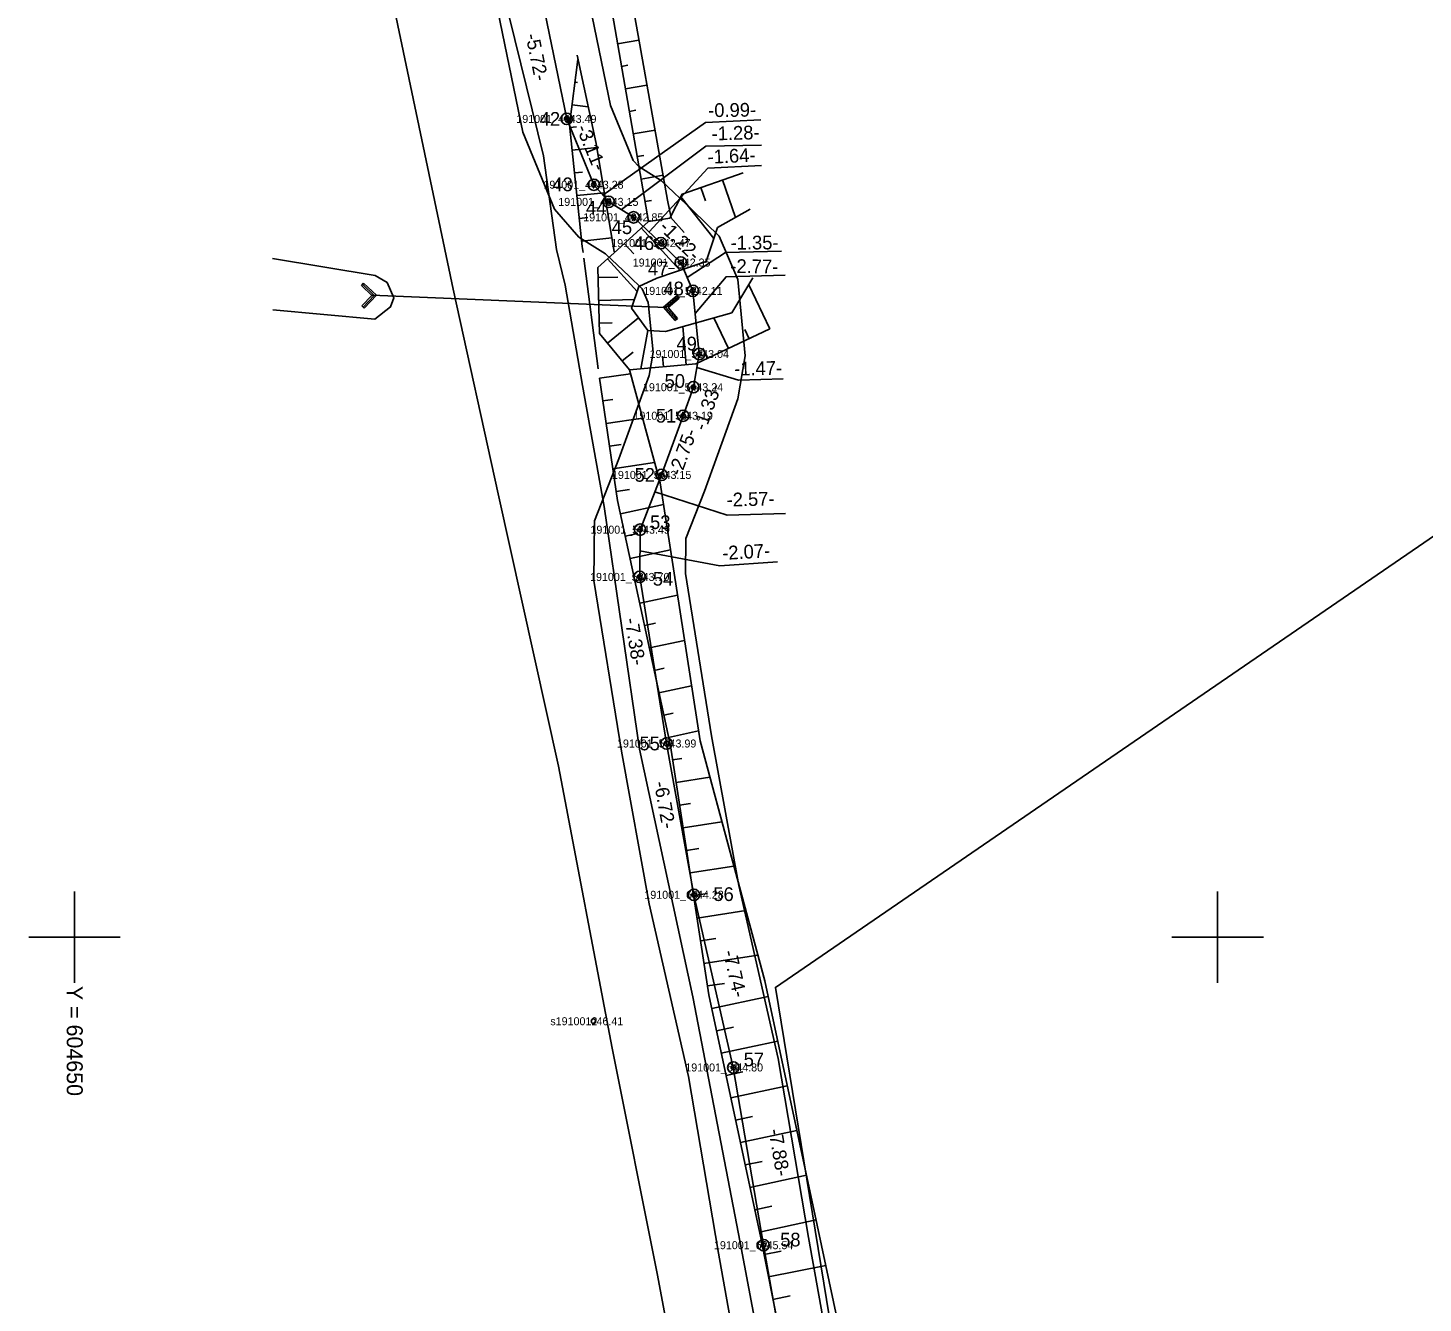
# Model space of a CAD drawing. Extents: x 604066 to 604956, y 6473634 to 6474346.
# Drawn here: x 604648 to 604709, y 6473734 to 6473789.8 of the extents above; entities that cross this region are included whole.
import ezdxf

# ---------------------------------------------------------------- set-up
doc = ezdxf.new("R2010")
doc.units = 0
for name, color, linetype in [('HALJASTUS', 7, 'Continuous'), ('JOONSIDE', 7, 'Continuous'), ('KOORDPUNKT', 7, 'Continuous'), ('MOOTKORG', 7, 'Continuous'), ('MOOTMPUNKT', 7, 'Continuous'), ('MOOTNR', 7, 'Continuous'), ('MOOTPIIR', 7, 'Continuous'), ('PIIR', 7, 'Continuous'), ('RELJEEF', 7, 'Continuous'), ('SITRASS', 7, 'Continuous'), ('TEE', 7, 'Continuous'), ('TRUUP', 7, 'Continuous'), ('VEEKOGU', 7, 'Continuous'), ('VORK', 7, 'Continuous')]:
    doc.layers.add(name, color=color, linetype=linetype)

msp = doc.modelspace()

# ---------------------------------------------------------------- linework, layer by layer
at = {"layer": 'HALJASTUS'}
msp.add_lwpolyline([(604673.598, 6473779.97), (604672.824, 6473784.706), (604671.983, 6473788.559)], dxfattribs=at)
at = {"layer": 'JOONSIDE'}
for points in [[(604673.105, 6473782.446), (604677.594, 6473785.615), (604680.025, 6473785.739)], [(604673.921, 6473781.809), (604677.611, 6473784.586), (604680.053, 6473784.632)], [(604675.133, 6473780.834), (604677.709, 6473783.622), (604680.053, 6473783.733)], [(604676.796, 6473778.845), (604678.469, 6473779.934), (604680.917, 6473779.999)], [(604677.146, 6473777.274), (604678.501, 6473778.872), (604681.081, 6473778.937)], [(604677.22, 6473774.9), (604679.04, 6473774.347), (604680.998, 6473774.409)], [(604675.391, 6473769.475), (604678.542, 6473768.445), (604681.105, 6473768.527)], [(604674.73, 6473766.892), (604678.232, 6473766.24), (604680.746, 6473766.403)]]:
    msp.add_lwpolyline(points, dxfattribs=at)
at = {"layer": 'KOORDPUNKT'}
for centre, radius in [((604671.53, 6473785.776), 0.25), ((604671.53, 6473785.776), 0.025), ((604671.53, 6473785.776), 0.0221), ((604671.53, 6473785.776), 0.0191), ((604671.53, 6473785.776), 0.0161), ((604671.53, 6473785.776), 0.0132), ((604671.53, 6473785.776), 0.0102), ((604671.53, 6473785.776), 0.00726), ((604671.53, 6473785.776), 0.0043), ((604672.715, 6473782.898), 0.25), ((604672.715, 6473782.898), 0.025), ((604672.715, 6473782.898), 0.0221), ((604672.715, 6473782.898), 0.0191), ((604672.715, 6473782.898), 0.0161), ((604672.715, 6473782.898), 0.0132), ((604672.715, 6473782.898), 0.0102), ((604672.715, 6473782.898), 0.00726), ((604672.715, 6473782.898), 0.0043), ((604673.365, 6473782.149), 0.25), ((604673.365, 6473782.149), 0.025), ((604673.365, 6473782.149), 0.0221), ((604673.365, 6473782.149), 0.0191), ((604673.365, 6473782.149), 0.0161), ((604673.365, 6473782.149), 0.0132), ((604673.365, 6473782.149), 0.0102), ((604673.365, 6473782.149), 0.00726), ((604673.365, 6473782.149), 0.0043), ((604674.456, 6473781.473), 0.25), ((604674.456, 6473781.473), 0.025), ((604674.456, 6473781.473), 0.0221), ((604674.456, 6473781.473), 0.0191), ((604674.456, 6473781.473), 0.0161), ((604674.456, 6473781.473), 0.0132), ((604674.456, 6473781.473), 0.0102), ((604674.456, 6473781.473), 0.00726), ((604674.456, 6473781.473), 0.0043), ((604675.648, 6473780.347), 0.25), ((604675.648, 6473780.347), 0.025), ((604675.648, 6473780.347), 0.0221), ((604675.648, 6473780.347), 0.0191), ((604675.648, 6473780.347), 0.0161), ((604675.648, 6473780.347), 0.0132), ((604675.648, 6473780.347), 0.0102), ((604675.648, 6473780.347), 0.00726), ((604675.648, 6473780.347), 0.0043), ((604676.518, 6473779.496), 0.25), ((604676.518, 6473779.496), 0.025), ((604676.518, 6473779.496), 0.0221), ((604676.518, 6473779.496), 0.0191), ((604676.518, 6473779.496), 0.0161), ((604676.518, 6473779.496), 0.0132), ((604676.518, 6473779.496), 0.0102), ((604676.518, 6473779.496), 0.00726), ((604676.518, 6473779.496), 0.0043), ((604677.048, 6473778.257), 0.25), ((604677.048, 6473778.257), 0.025), ((604677.048, 6473778.257), 0.0221), ((604677.048, 6473778.257), 0.0191), ((604677.048, 6473778.257), 0.0161), ((604677.048, 6473778.257), 0.0132), ((604677.048, 6473778.257), 0.0102), ((604677.048, 6473778.257), 0.00726), ((604677.048, 6473778.257), 0.0043), ((604677.324, 6473775.497), 0.25), ((604677.324, 6473775.497), 0.025), ((604677.324, 6473775.497), 0.0221), ((604677.324, 6473775.497), 0.0191), ((604677.324, 6473775.497), 0.0161), ((604677.324, 6473775.497), 0.0132), ((604677.324, 6473775.497), 0.0102), ((604677.324, 6473775.497), 0.00726), ((604677.324, 6473775.497), 0.0043), ((604677.07, 6473774.045), 0.25), ((604677.07, 6473774.045), 0.025), ((604677.07, 6473774.045), 0.0221), ((604677.07, 6473774.045), 0.0191), ((604677.07, 6473774.045), 0.0161), ((604677.07, 6473774.045), 0.0132), ((604677.07, 6473774.045), 0.0102), ((604677.07, 6473774.045), 0.00726), ((604677.07, 6473774.045), 0.0043), ((604676.621, 6473772.798), 0.25), ((604676.621, 6473772.798), 0.025), ((604676.621, 6473772.798), 0.0221), ((604676.621, 6473772.798), 0.0191), ((604676.621, 6473772.798), 0.0161), ((604676.621, 6473772.798), 0.0132), ((604676.621, 6473772.798), 0.0102), ((604676.621, 6473772.798), 0.00726), ((604676.621, 6473772.798), 0.0043), ((604675.68, 6473770.211), 0.25), ((604675.68, 6473770.211), 0.025), ((604675.68, 6473770.211), 0.0221), ((604675.68, 6473770.211), 0.0191), ((604675.68, 6473770.211), 0.0161), ((604675.68, 6473770.211), 0.0132), ((604675.68, 6473770.211), 0.0102), ((604675.68, 6473770.211), 0.00726), ((604675.68, 6473770.211), 0.0043), ((604674.738, 6473767.815), 0.25), ((604674.738, 6473767.815), 0.025), ((604674.738, 6473767.815), 0.0221), ((604674.738, 6473767.815), 0.0191), ((604674.738, 6473767.815), 0.0161), ((604674.738, 6473767.815), 0.0132), ((604674.738, 6473767.815), 0.0102), ((604674.738, 6473767.815), 0.00726), ((604674.738, 6473767.815), 0.0043), ((604674.721, 6473765.75), 0.25), ((604674.721, 6473765.75), 0.025), ((604674.721, 6473765.75), 0.0221), ((604674.721, 6473765.75), 0.0191), ((604674.721, 6473765.75), 0.0161), ((604674.721, 6473765.75), 0.0132), ((604674.721, 6473765.75), 0.0102), ((604674.721, 6473765.75), 0.00726), ((604674.721, 6473765.75), 0.0043), ((604675.898, 6473758.467), 0.25), ((604675.898, 6473758.467), 0.025), ((604675.898, 6473758.467), 0.0221), ((604675.898, 6473758.467), 0.0191), ((604675.898, 6473758.467), 0.0161), ((604675.898, 6473758.467), 0.0132), ((604675.898, 6473758.467), 0.0102), ((604675.898, 6473758.467), 0.00726), ((604675.898, 6473758.467), 0.0043), ((604677.095, 6473751.852), 0.25), ((604677.095, 6473751.852), 0.025), ((604677.095, 6473751.852), 0.0221), ((604677.095, 6473751.852), 0.0191), ((604677.095, 6473751.852), 0.0161), ((604677.095, 6473751.852), 0.0132), ((604677.095, 6473751.852), 0.0102), ((604677.095, 6473751.852), 0.00726), ((604677.095, 6473751.852), 0.0043), ((604678.816, 6473744.303), 0.25), ((604678.816, 6473744.303), 0.025), ((604678.816, 6473744.303), 0.0221), ((604678.816, 6473744.303), 0.0191), ((604678.816, 6473744.303), 0.0161), ((604678.816, 6473744.303), 0.0132), ((604678.816, 6473744.303), 0.0102), ((604678.816, 6473744.303), 0.00726), ((604678.816, 6473744.303), 0.0043), ((604680.141, 6473736.532), 0.25), ((604680.141, 6473736.532), 0.025), ((604680.141, 6473736.532), 0.0221), ((604680.141, 6473736.532), 0.0191), ((604680.141, 6473736.532), 0.0161), ((604680.141, 6473736.532), 0.0132), ((604680.141, 6473736.532), 0.0102), ((604680.141, 6473736.532), 0.00726), ((604680.141, 6473736.532), 0.0043)]:
    msp.add_circle(centre, radius, dxfattribs=at)
at = {"layer": 'MOOTMPUNKT'}
for centre in [(604671.53, 6473785.776), (604672.715, 6473782.898), (604673.365, 6473782.149), (604674.456, 6473781.473), (604675.648, 6473780.347), (604676.518, 6473779.496), (604677.048, 6473778.257), (604677.324, 6473775.497), (604677.07, 6473774.045), (604676.621, 6473772.798), (604675.68, 6473770.211), (604674.738, 6473767.815), (604674.721, 6473765.75), (604675.898, 6473758.467), (604677.095, 6473751.852), (604672.703, 6473746.324), (604678.816, 6473744.303), (604680.141, 6473736.532)]:
    msp.add_circle(centre, 0.1, dxfattribs=at)
at = {"layer": 'MOOTPIIR'}
for points in [[(604683.46, 6473729.306), (604682.111, 6473736.875), (604680.778, 6473744.694), (604679.055, 6473752.253), (604677.869, 6473758.805), (604676.722, 6473765.902), (604676.735, 6473767.428), (604677.551, 6473769.503), (604678.502, 6473772.117), (604679.01, 6473773.53), (604679.341, 6473775.423), (604679.008, 6473778.761), (604678.201, 6473780.648), (604677.034, 6473781.789), (604675.682, 6473783.066), (604674.677, 6473783.689), (604674.44, 6473783.962), (604673.451, 6473786.363), (604672.342, 6473791.755)], [(604668.412, 6473791.009), (604669.609, 6473785.189), (604670.99, 6473781.834), (604672.053, 6473780.609), (604673.23, 6473779.88), (604674.262, 6473778.905), (604674.835, 6473778.344), (604675.088, 6473777.753), (604675.307, 6473775.571), (604675.13, 6473774.56), (604674.74, 6473773.479), (604673.809, 6473770.919), (604672.741, 6473768.202), (604672.72, 6473765.598), (604673.927, 6473758.129), (604675.135, 6473751.451), (604676.854, 6473743.912), (604678.171, 6473736.189), (604679.54, 6473728.5)]]:
    msp.add_lwpolyline(points, dxfattribs=at)
at = {"layer": 'PIIR'}
msp.add_lwpolyline([(604833.54, 6473909.5), (604897.39, 6473936.49), (604953.49, 6473960.24), (604956.07, 6473961.29), (604940.8, 6473724.06), (604687.73, 6473704.56), (604680.66, 6473747.8), (604821.94, 6473844.68)], close=True, dxfattribs=at)
msp.add_lwpolyline([(604392.23, 6473874.61), (604414.7, 6473872.41), (604426.55, 6473871.03), (604444.65, 6473869.66), (604482.63, 6473866.81), (604486.98, 6473866.41), (604549.55, 6473854.82), (604575.16, 6473852.02), (604645.55, 6473867.92), (604659, 6473875.69), (604714.62, 6473889.17), (604776, 6473903.81), (604824.84, 6473905.94), (604833.54, 6473909.5), (604821.94, 6473844.68), (604680.66, 6473747.8), (604687.73, 6473704.56), (604422.99, 6473691.29), (604421.99, 6473694.09), (604395.15, 6473723.9)], dxfattribs=at)
at = {"layer": 'RELJEEF'}
for p, q in [((604673.757, 6473789.058), (604674.688, 6473789.219)), ((604673.927, 6473788.072), (604674.208, 6473788.121)), ((604671.894, 6473787.388), (604672, 6473787.374)), ((604674.098, 6473787.087), (604675.04, 6473787.25)), ((604671.765, 6473786.396), (604672.475, 6473786.304)), ((604674.269, 6473786.102), (604674.553, 6473786.151)), ((604671.662, 6473785.404), (604671.958, 6473785.435)), ((604674.44, 6473785.116), (604675.392, 6473785.282)), ((604671.767, 6473784.41), (604672.854, 6473784.524)), ((604674.611, 6473784.131), (604674.898, 6473784.181)), ((604671.872, 6473783.415), (604672.215, 6473783.451)), ((604674.781, 6473783.146), (604675.744, 6473783.313)), ((604678.342, 6473783.106), (604678.913, 6473781.471)), ((604671.977, 6473782.421), (604673.177, 6473782.547)), ((604674.952, 6473782.161), (604675.243, 6473782.211)), ((604676.521, 6473782.37), (604677.966, 6473780.549)), ((604677.398, 6473782.776), (604677.599, 6473782.201)), ((604672.082, 6473781.426), (604672.459, 6473781.466)), ((604674.785, 6473781.006), (604676.483, 6473779.156)), ((604676.065, 6473781.48), (604676.661, 6473780.813)), ((604672.186, 6473780.432), (604673.5, 6473780.57)), ((604674.048, 6473780.33), (604674.469, 6473779.871)), ((604673.308, 6473779.657), (604674.604, 6473778.223)), ((604672.908, 6473778.839), (604673.763, 6473778.86)), ((604680.412, 6473776.595), (604679.494, 6473778.527)), ((604672.932, 6473777.84), (604674.489, 6473777.877)), ((604672.956, 6473776.84), (604673.513, 6473776.853)), ((604673.32, 6473775.966), (604674.675, 6473777.075)), ((604676.76, 6473775.023), (604676.613, 6473776.696)), ((604678.606, 6473775.737), (604677.967, 6473777.08)), ((604674.768, 6473774.848), (604675.072, 6473776.521)), ((604679.509, 6473776.166), (604679.318, 6473776.568)), ((604673.953, 6473775.192), (604674.432, 6473775.584)), ((604677.702, 6473775.307), (604677.489, 6473775.756)), ((604675.764, 6473774.935), (604675.723, 6473775.403)), ((604672.964, 6473774.437), (604674.316, 6473774.637)), ((604673.11, 6473773.448), (604673.551, 6473773.513)), ((604673.256, 6473772.458), (604674.843, 6473772.693)), ((604673.403, 6473771.469), (604673.914, 6473771.545)), ((604673.549, 6473770.48), (604675.37, 6473770.749)), ((604673.695, 6473769.491), (604674.274, 6473769.576)), ((604673.879, 6473768.508), (604675.758, 6473768.913)), ((604674.09, 6473767.531), (604674.637, 6473767.649)), ((604674.301, 6473766.553), (604676.065, 6473766.934)), ((604674.512, 6473765.576), (604675.024, 6473765.686)), ((604674.722, 6473764.598), (604676.373, 6473764.954)), ((604674.933, 6473763.621), (604675.411, 6473763.724)), ((604675.144, 6473762.643), (604676.681, 6473762.974)), ((604675.355, 6473761.666), (604675.799, 6473761.761)), ((604675.565, 6473760.688), (604676.988, 6473760.995)), ((604675.776, 6473759.711), (604676.186, 6473759.799)), ((604675.987, 6473758.733), (604677.296, 6473759.015)), ((604676.161, 6473757.749), (604676.572, 6473757.812)), ((604676.314, 6473756.76), (604677.793, 6473756.989)), ((604676.466, 6473755.772), (604676.943, 6473755.846)), ((604676.619, 6473754.784), (604678.317, 6473755.046)), ((604676.771, 6473753.795), (604677.313, 6473753.879)), ((604676.924, 6473752.807), (604678.84, 6473753.103)), ((604677.076, 6473751.819), (604677.684, 6473751.913)), ((604677.229, 6473750.831), (604679.363, 6473751.16)), ((604677.381, 6473749.842), (604678.054, 6473749.946)), ((604677.534, 6473748.854), (604679.887, 6473749.217)), ((604677.686, 6473747.866), (604678.425, 6473747.98)), ((604677.873, 6473746.884), (604680.337, 6473747.41)), ((604678.082, 6473745.906), (604678.822, 6473746.064)), ((604678.291, 6473744.928), (604680.758, 6473745.454)), ((604678.5, 6473743.95), (604679.24, 6473744.108)), ((604678.708, 6473742.972), (604681.179, 6473743.499)), ((604678.917, 6473741.994), (604679.659, 6473742.152)), ((604679.126, 6473741.016), (604681.6, 6473741.544)), ((604679.335, 6473740.038), (604680.077, 6473740.197)), ((604679.544, 6473739.06), (604682.021, 6473739.589)), ((604679.752, 6473738.082), (604680.496, 6473738.241)), ((604679.961, 6473737.104), (604682.442, 6473737.634)), ((604680.16, 6473736.124), (604680.909, 6473736.273)), ((604680.355, 6473735.143), (604682.865, 6473735.643)), ((604680.551, 6473734.163), (604681.307, 6473734.313))]:
    msp.add_line(p, q, dxfattribs=at)
for points in [[(604653.295, 6473883.776), (604652.349, 6473882.704), (604651.554, 6473874.934), (604652.409, 6473867.668), (604653.905, 6473857.515), (604657.906, 6473844.822), (604660.747, 6473842.118), (604667.575, 6473831.749), (604666.639, 6473827.232), (604667.872, 6473819.034), (604671.628, 6473805.551), (604673.035, 6473793.22), (604675.102, 6473781.297)], [(604668.878, 6473831.498), (604668.326, 6473826.862), (604669.23, 6473819.524), (604672.734, 6473805.555), (604674.05, 6473792.791), (604675.939, 6473782.22), (604676.105, 6473781.446)], [(604672.022, 6473788.38), (604671.651, 6473785.513), (604672.211, 6473780.197), (604672.245, 6473779.94)], [(604675.102, 6473781.297), (604676.043, 6473781.437), (604676.583, 6473782.492), (604679.244, 6473783.42)], [(604680.412, 6473776.595), (604677.182, 6473775.06), (604674.271, 6473774.804), (604672.967, 6473776.398), (604672.897, 6473779.286), (604673.752, 6473780.058), (604675.102, 6473781.297)], [(604672.278, 6473779.683), (604672.91, 6473774.853)], [(604672.964, 6473774.437), (604673.755, 6473769.085), (604676.065, 6473758.371), (604677.745, 6473747.484), (604680.015, 6473736.852), (604681.936, 6473727.206), (604682.488, 6473725.191), (604683.769, 6473718.464), (604685.268, 6473712.216), (604687.251, 6473697.629), (604689.629, 6473693.548), (604694.355, 6473690.407), (604698.464, 6473689.524)], [(604674.271, 6473774.804), (604675.61, 6473769.864), (604677.362, 6473758.59), (604680.189, 6473748.095), (604682.491, 6473737.405), (604685.004, 6473725.567), (604685.959, 6473718.549), (604686.885, 6473712.629), (604687.127, 6473704.438), (604689.157, 6473697.674), (604693.127, 6473694.128), (604698.019, 6473692.845)]]:
    msp.add_lwpolyline(points, dxfattribs=at)
at = {"layer": 'SITRASS'}
msp.add_lwpolyline([(604670.377, 6473791.382), (604671.53, 6473785.776), (604672.715, 6473782.898), (604673.365, 6473782.149), (604674.456, 6473781.473), (604675.648, 6473780.347), (604676.518, 6473779.496), (604677.048, 6473778.257), (604677.324, 6473775.497), (604677.07, 6473774.045), (604676.621, 6473772.798), (604675.68, 6473770.211), (604674.738, 6473767.815), (604674.721, 6473765.75), (604675.898, 6473758.467), (604677.095, 6473751.852), (604678.816, 6473744.303), (604680.141, 6473736.532), (604681.5, 6473728.903)], dxfattribs=at)
at = {"layer": 'TEE'}
for points in [[(604658.81, 6473832.593), (604663.41, 6473815.739), (604666.276, 6473803.944), (604668.262, 6473793.278), (604670.517, 6473784.167), (604671.08, 6473780.073), (604671.455, 6473778.507), (604672.217, 6473774.119), (604673.164, 6473768.835), (604674.714, 6473758.225), (604677.044, 6473747.391), (604679.117, 6473736.654), (604680.917, 6473727.059), (604681.455, 6473724.996), (604682.501, 6473718.343), (604684.444, 6473711.751), (604685.117, 6473704.62), (604685.813, 6473699.835), (604686.179, 6473697.568), (604688.712, 6473692.868), (604693.859, 6473689.574), (604697.868, 6473688.858)], [(604654.602, 6473831.658), (604658.704, 6473815.393), (604661.338, 6473804.068), (604663.574, 6473792.578), (604666.567, 6473778.333), (604668.535, 6473769.378), (604671.171, 6473757.479), (604673.518, 6473745.143), (604675.484, 6473735.292), (604677.447, 6473724.836), (604678.32, 6473717.488), (604681.05, 6473699.828), (604680.918, 6473696.769), (604679.22, 6473692.841), (604676.23, 6473689.347), (604671.943, 6473687.313)]]:
    msp.add_lwpolyline(points, dxfattribs=at)
at = {"layer": 'TRUUP'}
for p, q in [((604662.55, 6473778.497), (604662.648, 6473778.6)), ((604663.112, 6473778.062), (604662.599, 6473778.549)), ((604663.213, 6473778.065), (604662.648, 6473778.6)), ((604663.011, 6473778.059), (604662.55, 6473778.497)), ((604662.574, 6473777.598), (604663.011, 6473778.059)), ((604662.625, 6473777.549), (604663.112, 6473778.062)), ((604662.677, 6473777.5), (604663.213, 6473778.065)), ((604663.011, 6473778.067), (604675.866, 6473777.537)), ((604676.355, 6473778.052), (604675.766, 6473777.544)), ((604676.402, 6473777.998), (604675.866, 6473777.537)), ((604676.448, 6473777.945), (604675.966, 6473777.53)), ((604676.448, 6473777.945), (604676.355, 6473778.052)), ((604662.574, 6473777.598), (604662.677, 6473777.5)), ((604675.766, 6473777.544), (604676.274, 6473776.955)), ((604675.866, 6473777.537), (604676.327, 6473777.001)), ((604675.966, 6473777.53), (604676.381, 6473777.048)), ((604676.381, 6473777.048), (604676.274, 6473776.955))]:
    msp.add_line(p, q, dxfattribs=at)
at = {"layer": 'VEEKOGU'}
for points in [[(604679.548, 6473781.829), (604678.124, 6473781.026), (604677.627, 6473779.547), (604676.374, 6473779.119)], [(604658.662, 6473779.671), (604663.149, 6473778.929), (604663.679, 6473778.616), (604663.966, 6473777.959), (604663.815, 6473777.559), (604663.134, 6473777.019), (604658.678, 6473777.434)], [(604676.374, 6473779.119), (604676.248, 6473779.076), (604675.467, 6473778.809), (604674.68, 6473778.454), (604674.366, 6473777.505), (604675.072, 6473776.521), (604675.857, 6473776.481), (604678.745, 6473777.301), (604679.674, 6473778.821)]]:
    msp.add_lwpolyline(points, dxfattribs=at)
at = {"layer": 'VORK'}
for p, q in [((604650, 6473752), (604650, 6473748)), ((604700, 6473752), (604700, 6473748)), ((604648, 6473750), (604652, 6473750)), ((604698, 6473750), (604702, 6473750))]:
    msp.add_line(p, q, dxfattribs=at)

# ---------------------------------------------------------------- texts
at = {"layer": 'JOONSIDE'}
for s, rotation, p in [('-5.72-', 281.6221, (604669.721, 6473789.447)), ('-0.99-', 0.68163, (604677.72, 6473785.854)), ('-3.11-', 292.37913, (604671.933, 6473785.388)), ('-1.28-', 1.73188, (604677.876, 6473784.831)), ('-1.64-', 2.51179, (604677.703, 6473783.814)), ('-1.22-', 315.63253, (604675.535, 6473780.985)), ('-1.35-', 0.31469, (604678.699, 6473780.062)), ('-2.77-', 359.21622, (604678.683, 6473779.045)), ('-1.47-', 1.12146, (604678.857, 6473774.552)), ('-1.33-', 70.19787, (604677.604, 6473772.105)), ('-2.75-', 70.01156, (604676.528, 6473770.129)), ('-2.57-', 1.52598, (604678.532, 6473768.823)), ('-2.07-', 3.31281, (604678.35, 6473766.49)), ('-7.38-', 279.18015, (604674.063, 6473763.915)), ('-6.72-', 280.25682, (604675.341, 6473756.762)), ('-7.74-', 282.84264, (604678.362, 6473749.366)), ('-7.88-', 279.67621, (604680.354, 6473741.573))]:
    msp.add_text(s, height=0.6, rotation=rotation, dxfattribs=at).set_placement(p)
at = {"layer": 'KOORDPUNKT'}
for s, p in [('42 ', (604670.348, 6473785.476)), ('43 ', (604670.903, 6473782.614)), ('44 ', (604672.373, 6473781.588)), ('45 ', (604673.498, 6473780.739)), ('46 ', (604674.461, 6473780.047)), ('47 ', (604675.079, 6473778.935)), ('48 ', (604675.759, 6473778.06)), ('49 ', (604676.33, 6473775.654)), ('50 ', (604675.81, 6473774.017)), ('51 ', (604675.429, 6473772.498)), ('52 ', (604674.498, 6473769.911)), ('53 ', (604675.175, 6473767.842)), ('54 ', (604675.296, 6473765.368)), ('55 ', (604674.711, 6473758.167)), ('56 ', (604677.942, 6473751.58)), ('57 ', (604679.27, 6473744.353)), ('58 ', (604680.865, 6473736.477))]:
    msp.add_text(s, height=0.6, dxfattribs=at).set_placement(p)
at = {"layer": 'MOOTKORG'}
for s, p in [(' 43.49', (604671.53, 6473785.601)), (' 43.28', (604672.715, 6473782.723)), (' 43.15', (604673.365, 6473781.974)), (' 42.85', (604674.456, 6473781.298)), (' 42.47', (604675.648, 6473780.172)), (' 42.35', (604676.518, 6473779.321)), (' 42.11', (604677.048, 6473778.082)), (' 43.04', (604677.324, 6473775.322)), (' 43.24', (604677.07, 6473773.87)), (' 43.19', (604676.621, 6473772.623)), (' 43.15', (604675.68, 6473770.036)), (' 43.49', (604674.738, 6473767.64)), (' 43.70', (604674.721, 6473765.575)), (' 43.99', (604675.898, 6473758.292)), (' 44.28', (604677.095, 6473751.677)), (' 46.41', (604672.703, 6473746.149)), (' 44.80', (604678.816, 6473744.128)), (' 45.54', (604680.141, 6473736.357))]:
    msp.add_text(s, height=0.35, dxfattribs=at).set_placement(p)
at = {"layer": 'MOOTNR'}
for s, p in [('191001_46 ', (604669.325, 6473785.601)), ('191001_47 ', (604670.51, 6473782.723)), ('191001_48 ', (604671.16, 6473781.974)), ('191001_49 ', (604672.251, 6473781.298)), ('191001_50 ', (604673.478, 6473780.172)), ('191001_51 ', (604674.418, 6473779.321)), ('191001_52 ', (604674.878, 6473778.082)), ('191001_53 ', (604675.154, 6473775.322)), ('191001_54 ', (604674.865, 6473773.87)), ('191001_55 ', (604674.451, 6473772.623)), ('191001_56 ', (604673.51, 6473770.036)), ('191001_57 ', (604672.568, 6473767.64)), ('191001_58 ', (604672.551, 6473765.575)), ('191001_59 ', (604673.728, 6473758.292)), ('191001_60 ', (604674.925, 6473751.677)), ('s1910012 ', (604670.813, 6473746.149)), ('191001_61 ', (604676.716, 6473744.128)), ('191001_62 ', (604677.971, 6473736.357))]:
    msp.add_text(s, height=0.35, dxfattribs=at).set_placement(p)
at = {"layer": 'VORK'}
msp.add_text('Y = 604650 ', height=0.7, rotation=270, dxfattribs=at).set_placement((604649.66, 6473747.869))

doc.saveas('drawing.dxf')
